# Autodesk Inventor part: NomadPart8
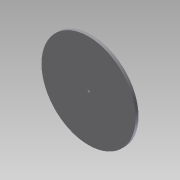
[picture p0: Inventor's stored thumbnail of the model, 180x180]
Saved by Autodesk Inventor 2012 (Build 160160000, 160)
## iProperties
Created: 2012-10
Part Number: NomadPart8
Material: Default
Document SubType Name: Modeling
Designer: TechShop Member
Density: 1 g/cm^3
Author: TechShop Member
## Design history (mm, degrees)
sketch "Sketch1"
  geometry: C1 r 104.775 at (0, 0); 1 further point
  constraints: 1 centre point, 1 coincident
  dimensions: "d0" = 209.55 diameter of C1
extrude "Extrusion1" new body sketch "Sketch1" distance "d1" = 6.35; taper "d2" = 0 deg
sketch "Sketch2"
  geometry: C1 r 104.775 at (0, 0) reference; 1 further point
  constraints: 1 coincident
hole "Hole1" sketch "Sketch2" at (0, 0) diameter "d3" = 5.207; stored, may be unused: countersink angle "d7" = 82 deg, drill point angle "d9" = 118 deg; dims "d4" = 19.05, "d5" = 9.525, "d6" = 6.35, "d8" = 25.4
body "Solid1"
